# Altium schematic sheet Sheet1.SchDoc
size A4
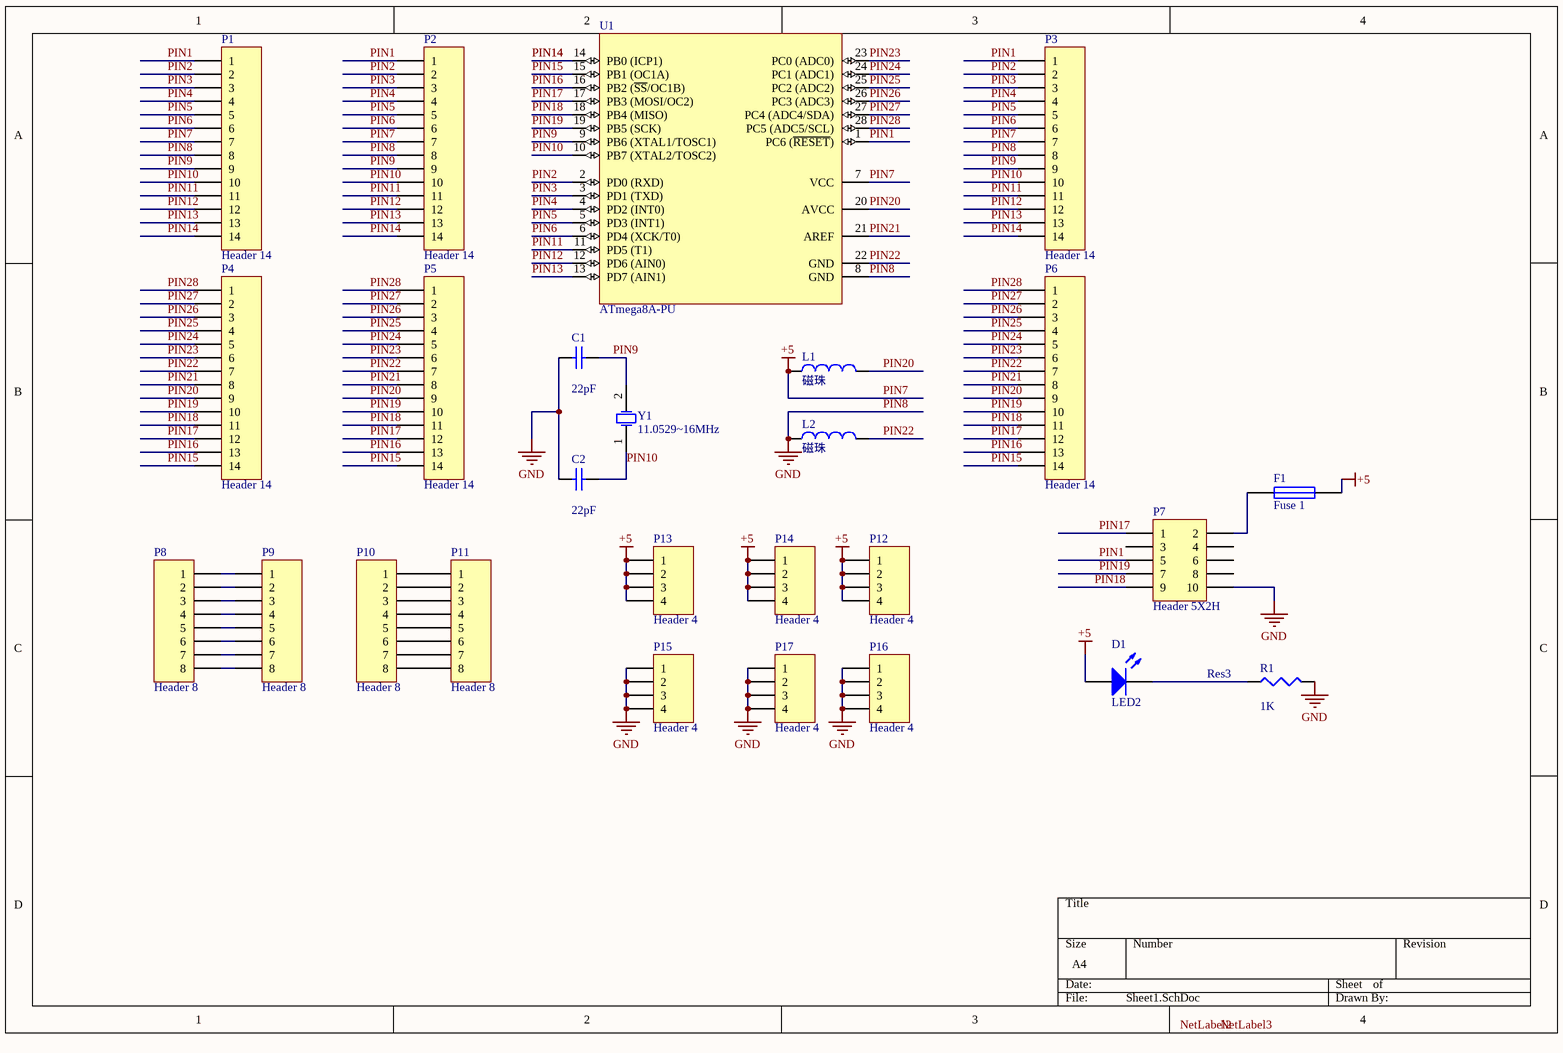
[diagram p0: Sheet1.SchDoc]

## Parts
C1  value 22pF  [6-0805_N]  (hidden comment: Cap Semi)
C2  value 22pF  [6-0805_N]  (hidden comment: Cap Semi)
D1  LED2  [6-0805_N]
F1  Fuse 1  [6-0805_N]
L1  磁珠  [6-0805_N]
L2  磁珠  [6-0805_N]
P1  Header 14  [HDR1X14]
P2  Header 14  [HDR1X14]
P3  Header 14  [HDR1X14]
P4  Header 14  [HDR1X14]
P5  Header 14  [HDR1X14]
P6  Header 14  [HDR1X14]
P7  Header 5X2H  [HDR2X5H]
P8  Header 8  [HDR1X8]
P9  Header 8  [HDR1X8]
P10  Header 8  [HDR1X8]
P11  Header 8  [HDR1X8]
P12  Header 4  [HDR1X4]
P13  Header 4  [HDR1X4]
P14  Header 4  [HDR1X4]
P15  Header 4  [HDR1X4]
P16  Header 4  [HDR1X4]
P17  Header 4  [HDR1X4]
R1  Res3  value 1K  [6-0805_N]
U1  ATmega8A-PU  [28P3]
Y1  11.0529~16MHz  [R38]

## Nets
PIN7: D1.1(A) F1.2 L1.1 P1.7 P2.7 P3.7 P12.1 P12.2 P12.3 P12.4 P13.1 P13.2 P13.3 P13.4 P14.1 P14.2 P14.3 P14.4 U1.7(VCC)  [also labelled +5]
PIN8: C1.1 C2.1 L2.1 P1.8 P2.8 P3.8 P7.10 P15.1 P15.2 P15.3 P15.4 P16.1 P16.2 P16.3 P16.4 P17.1 P17.2 P17.3 P17.4 R1.2 U1.8(GND)  [also labelled GND]
PIN1: P1.1 P2.1 P3.1 P7.5 U1.1(PC6_(~{RESET}))
PIN2: P1.2 P2.2 P3.2 U1.2(PD0_(RXD))
PIN3: P1.3 P2.3 P3.3 U1.3(PD1_(TXD))
PIN4: P1.4 P2.4 P3.4 U1.4(PD2_(INT0))
PIN5: P1.5 P2.5 P3.5 U1.5(PD3_(INT1))
PIN6: P1.6 P2.6 P3.6 U1.6(PD4_(XCK/T0))
PIN9: C1.2 P1.9 P2.9 P3.9 U1.9(PB6_(XTAL1/TOSC1)) Y1.2(OSC2)
PIN10: C2.2 P1.10 P2.10 P3.10 U1.10(PB7_(XTAL2/TOSC2)) Y1.1(OSC1)
PIN11: P1.11 P2.11 P3.11 U1.11(PD5_(T1))
PIN12: P1.12 P2.12 P3.12 U1.12(PD6_(AIN0))
PIN13: P1.13 P2.13 P3.13 U1.13(PD7_(AIN1))
PIN14: P1.14 P2.14 P3.14 U1.14(PB0_(ICP1))
PIN15: P4.14 P5.14 P6.14 U1.15(PB1_(OC1A))
PIN16: P4.13 P5.13 P6.13 U1.16(PB2_(~{SS}/OC1B))
PIN17: P4.12 P5.12 P6.12 P7.1 U1.17(PB3_(MOSI/OC2))
PIN18: P4.11 P5.11 P6.11 P7.9 U1.18(PB4_(MISO))
PIN19: P4.10 P5.10 P6.10 P7.7 U1.19(PB5_(SCK))
PIN20: L1.2 P4.9 P5.9 P6.9 U1.20(AVCC)
PIN21: P4.8 P5.8 P6.8 U1.21(AREF)
PIN22: L2.2 P4.7 P5.7 P6.7 U1.22(GND)
PIN23: P4.6 P5.6 P6.6 U1.23(PC0_(ADC0))
PIN24: P4.5 P5.5 P6.5 U1.24(PC1_(ADC1))
PIN25: P4.4 P5.4 P6.4 U1.25(PC2_(ADC2))
PIN26: P4.3 P5.3 P6.3 U1.26(PC3_(ADC3))
PIN27: P4.2 P5.2 P6.2 U1.27(PC4_(ADC4/SDA))
PIN28: P4.1 P5.1 P6.1 U1.28(PC5_(ADC5/SCL))
NetD1_2: D1.2(K) R1.1
NetF1_1: F1.1 P7.2
NetP8_1: P8.1 P9.1
NetP8_2: P8.2 P9.2
NetP8_3: P8.3 P9.3
NetP8_4: P8.4 P9.4
NetP8_5: P8.5 P9.5
NetP8_6: P8.6 P9.6
NetP8_7: P8.7 P9.7
NetP8_8: P8.8 P9.8
NetP10_1: P10.1 P11.1
NetP10_2: P10.2 P11.2
NetP10_3: P10.3 P11.3
NetP10_4: P10.4 P11.4
NetP10_5: P10.5 P11.5
NetP10_6: P10.6 P11.6
NetP10_7: P10.7 P11.7
NetP10_8: P10.8 P11.8

Not connected (* = marked no-connect by the designer): P7 3 4 6 8

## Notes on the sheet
- Labels drawn without touching a wire or pin: NetLabel2, NetLabel3

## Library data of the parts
C1 C2 = Cap Semi: Capacitor (Semiconductor SIM Model)
D1 = LED2: Typical RED, GREEN, YELLOW, AMBER GaAs LED
F1 = Fuse 1: 5V 500mA
L1 L2 = Inductor: Code_IEC: 1005
P1-P6 = Header 14: Header, 14-Pin
P7 = Header 5X2H: Header, 5-Pin, Dual row, Right Angle
P8-P11 = Header 8: Header, 8-Pin
P12-P17 = Header 4: Header, 4-Pin
R1 = Res3: Resistor
U1 = ATmega8A-PU: 8-bit AVR Microcontroller, 2.7-5.5V, 16MHz, 8KB Flash, 512 Bytes EEPROM, 1KB SRAM, 28-pin PDIP, Industrial Grade (-40°C to 85°C)
Y1 = XTAL: Crystal Oscillator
